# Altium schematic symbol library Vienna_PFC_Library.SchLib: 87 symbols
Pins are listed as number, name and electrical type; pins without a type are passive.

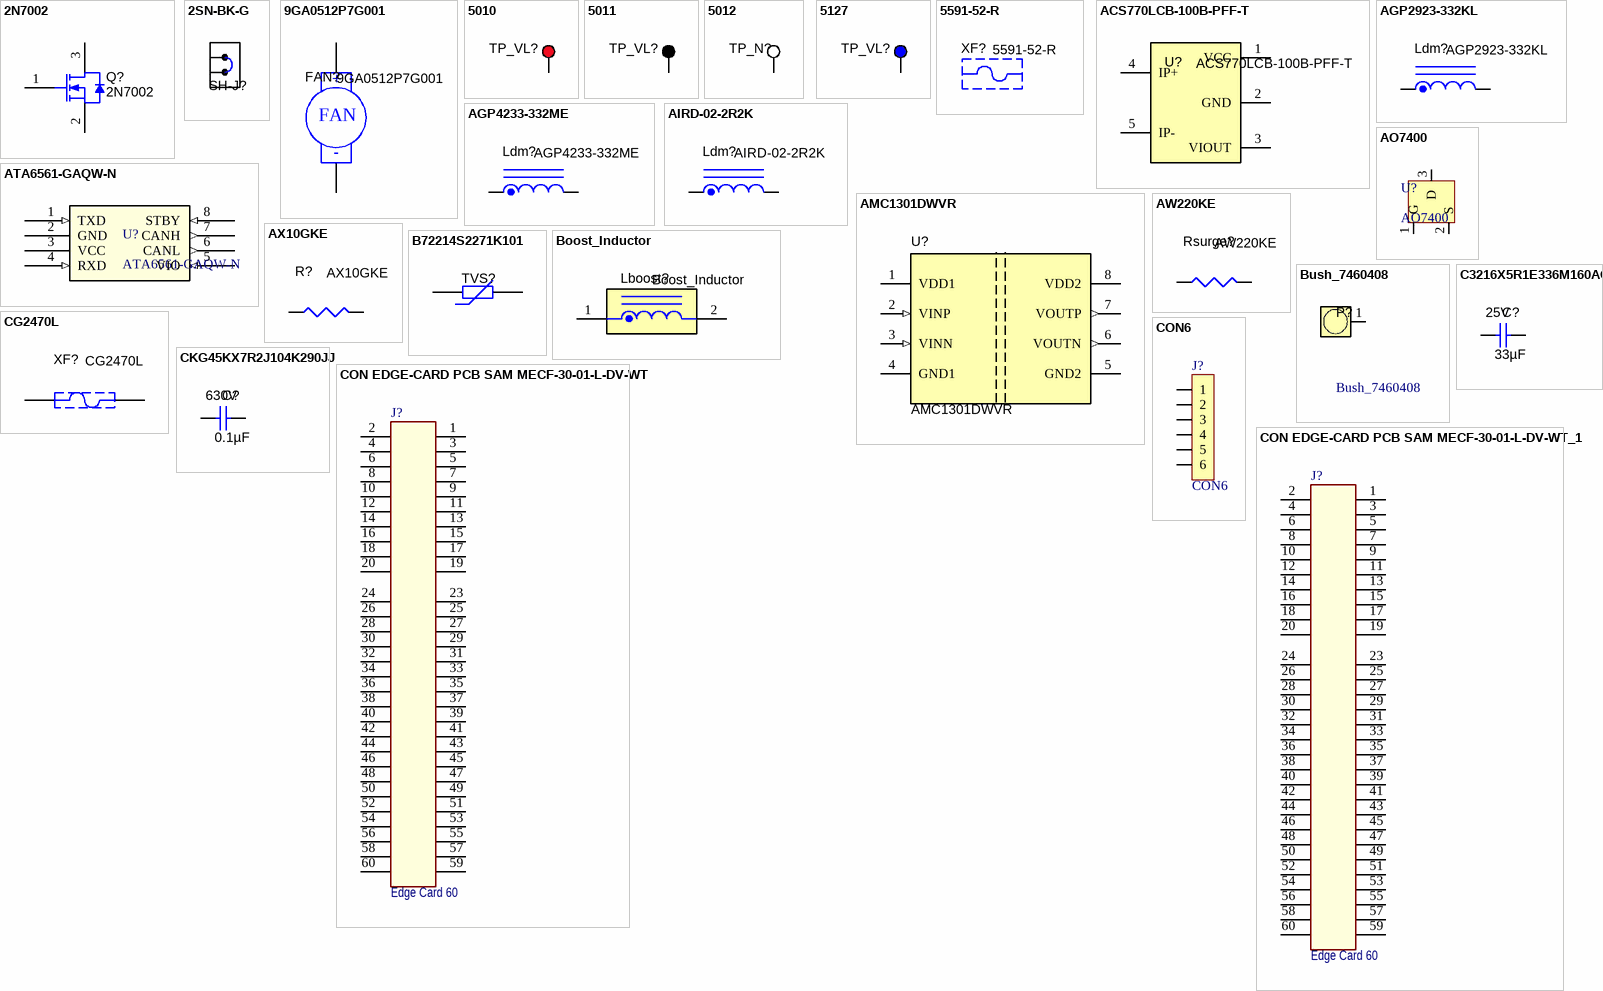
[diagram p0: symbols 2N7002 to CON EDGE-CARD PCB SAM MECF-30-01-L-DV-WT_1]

## 2N7002
designator Q?
MOSFET, N-CH, 60 V, 115 MA, SOT-23; Manufacturer: Fairchild Semiconductor; Alternate Manufacturer: None; U/M: EA; ChType: N; Value: 60V; VdsMax_V: 60; Value1: ? ohm; Value2: ? nC; Vgs_V: 20; IdsMax_A: 115; SizeAreaWB_mm2: 14; SizeArea_mm2: 7.5; SizeX_mm: 2.5; SizeY_mm: 3; SizeZ_mm: 1.1; AEC Category: Q101
footprint SOT-23 (SOT23, 3-Leads, Body 2.9x1.3mm, Pitch 0.95mm, Lead Span 2.5mm, IPC Medium Density)
footprint SOT-23M
footprint SOT-23L
pins: 1 G, 2 S, 3 D

## 2SN-BK-G
designator SH-J?  (value not drawn)
Shunt, 2mm, Gold plated, Black; Manufacturer: Samtec; Value: 1x2; Note: You can "mate" this to a header by matching the designator.  i.e. use SH-J3 for header J3
footprint 2SN-BK-G

## 9GA0512P7G001
designator FAN?
FAN 52X15MM 12VDC TACH,PWM; Manufacturer: Sanyo Denki America Inc.; CompType: DC Fans
pins: 1 +, 2 -

## 5010
designator TP_VL?  (value not drawn)
Test Point, Multipurpose, Red, TH; Manufacturer: Keystone; CompType: Test Point Loop; ContactFinish: Silver
footprint Keystone5010 (Keystone Multipurpose loops)
pins: 1

## 5011
designator TP_VL?  (value not drawn)
Test Point, Multipurpose, Black, TH; Manufacturer: Keystone; CompType: Test Point Loop; ContactFinish: Silver
footprint Keystone5011 (Keystone Multipurpose loops)
pins: 1

## 5012
designator TP_N?  (value not drawn)
Test Point, Multipurpose, White, TH; Manufacturer: Keystone; CompType: Test Point Loop; ContactFinish: Silver
footprint Keystone5012 (Keystone Multipurpose loops)
pins: 1

## 5127
designator TP_VL?  (value not drawn)
Test Point, Multipurpose, Blue, TH; Manufacturer: Keystone; CompType: Test Point Loop; U/M: EA; ContactFinish: Silver
footprint Keystone5127 (Keystone Multipurpose loops)
pins: 1

## 5591-52-R
designator XF?
FUSE CLIP CARTRIDGE CHASSIS MNT, Eaton; CompType: Fuse Holder

## ACS770LCB-100B-PFF-T
designator U?
SENSOR CURRENT HALL 100A AC/DC; Manufacturer: Allegro MicroSystems, LLC; CompType: Current Transducers
footprint ACS770
pins: 1 VCC, 2 GND, 3 VIOUT, 4 IP+, 5 IP-

## AGP2923-332KL
designator Ldm?
FIXED IND 3.3UH 19A 4  TH, Coilcraft; CompType: Fixed Inductors
footprint AGP2923 (Inductor)
pins: 1, 2

## AGP4233-332ME
designator Ldm?
FIXED IND 3.3UH 34A  TH, Coilcraft; CompType: Fixed Inductors
footprint AGP4233-332ME (Inductor)
pins: 1, 2

## AIRD-02-2R2K
designator Ldm?
FIXED IND 2.2UH 11.4A 4 MOHM TH, Abracon LLC; CompType: Fixed Inductors
footprint FuseHolder_65800001009
pins: 1, 2

## AMC1301DWVR
designator U?
Precision +/-250-mV Input, 3-us Delay, Reinforced Isolated Amplifier, DWV0008A (SOIC-8); Manufacturer: Texas Instruments; SymbolCreator: Altium; SizeArea_mm2: 67.275; SizeAreaWB_mm2: 105.975; SizeX_mm: 11.5; SizeY_mm: 5.85; SizeZ_mm: 2.8; CompType: IC; U/M: EA
footprint AMC1301 (SOIC, 8-Leads, Body 5.95x7.6mm (max), Pitch 1.27mm)
pins: 1 VDD1 (power), 2 VINP (in), 3 VINN (in), 4 GND1 (power), 5 GND2 (power), 6 VOUTN (out), 7 VOUTP (out), 8 VDD2 (power)

## AO7400
designator U?
MOSFET N-CH 30V 1.7A SC70-3@785-1084-1-ND
footprint AO7400_SC-70-3L
pins: 1 G, 2 S, 3 D

## ATA6561-GAQW-N
designator U?
CAN Interface IC Industrial Grade CAN TRX with VIO PIN (SO8); Manufacturer: Microchip Technology / Atmel; GENERIC_PART_NUMBER: SN65HVD234; INDUSTRY_STD_PKG_TYPE: SOIC; PIN_COUNT: 8; PACKAGE_DESIGNATOR: D; Vendor: Mouser
footprint SOIC8
pins: 1 TXD (in), 2 GND (power), 3 VCC (power), 4 RXD (in), 5 VIO (in), 6 CANL (out), 7 CANH (out), 8 STBY (in)

## AW220KE
designator Rsurge?
RES 22 OHM 2.5W 10% RADIAL; Manufacturer: Ohmite; CompType: Through Hole Resistors
footprint AW220KE (Capacitor)
pins: 1, 2

## AX10GKE
designator R?
RES 1 OHM 3.5W 10% RADIAL; Manufacturer: Ohmite; CompType: Through Hole Resistors
footprint AX10GKE (Res)
pins: 1, 2

## B72214S2271K101
designator TVS?  (value not drawn)
VARISTOR 430V 6KA DISC 14MM, EPCOS (TDK); CompType: TVS - Varistors, MOVs
footprint B72214S2271K101 (Capacitor)
pins: 1, 2

## Boost_Inductor
designator Lboost?
Boost_Inductor, Handmake
footprint Boost_Inductor
pins: 1, 2

## Bush_7460408
designator P?
TERM PWR ELEMENT M5 12 PIN PCB; Manufacturer: Wurth Electronics Inc.
footprint Bush7460408 (Power Connecter 12pin)
pins: 1 (power) "Voltage input"

## C3216X5R1E336M160AC
designator C?  VDC_V: 25V  ValueDisplayed: 33µF  (hidden comment: C3216X5R1E336M160AC)
CAP, CERM, 33 µF, 25 V, +/- 20%, X5R, 1206; Manufacturer: TDK; Polarized: N; CompType: Capacitor; Value: 33uF; U/M: EA; Tolerance_%: 20; Value1: Unknown; TaMin_C: -55; TaMax_C: 85; Cap_Case: 1206; AEC Category: Q200
signal-integrity model Cap
simulation model Cap
footprint 0805_HV (0805 with 30mil clearance between pads)
pins: 1, 2

## CG2470L
designator XF?
GDT 470V 20KA THROUGH HOLE,  Littelfuse Inc.; CompType: Gas Discharge Tube Arresters (GDT)
footprint CG2470L (Capacitor)
pins: 1, 2

## CKG45KX7R2J104K290JJ
designator C?  VDC_V: 630V  ValueDisplayed: 0.1µF  (hidden comment: CKG45KX7R2J104K290JJ)
CAP, CERM, 0.1 µF, 630V, +/- 10%, X7R, 1206; Value: 33uF; Value1: Unknown; AEC Category: Q200
signal-integrity model Cap
simulation model Cap
footprint 1812 (SMD, 2-Leads, Body 4.8x3.4mm)
pins: 1, 2

## CON6
designator J?
Connector
pins: 1, 2, 3, 4, 5, 6

## CON EDGE-CARD PCB SAM MECF-30-01-L-DV-WT
designator J?  value Edge Card 60  (hidden comment: CON EDGE-CARD PCB SAM MECF-30-01-L-DV-WT)  (no BOM)
MCHP-ID: CON1706; Description_: CON_EDGE-CARD_PCB_SAM_MECF-30-01-L-DV-WT; Dev Tools Status: Design; Owner: Tim Moffat; Populated: YES
footprint CON_EDGE-CARD_PCB_SAM_MECF-30-01-L-DV-WT
footprint CardEdgeConnector60Pin
pins: 1, 2, 3, 4, 5, 6, 7, 8, 9, 10, 11, 12, 13, 14, 15, 16, 17, 18, 19, 20, 23, 24, 25, 26, 27, 28, 29, 30, 31, 32, 33, 34, 35, 36, 37, 38, 39, 40, 41, 42, 43, 44, 45, 46, 47, 48, 49, 50, 51, 52, 53, 54, 55, 56, 57, 58, 59, 60

## CON EDGE-CARD PCB SAM MECF-30-01-L-DV-WT_1
designator J?, comment value Edge Card 60  (hidden comment: CON EDGE-CARD PCB SAM MECF-30-01-L-DV-WT)  (no BOM)
MCHP-ID: CON1706; Description_: CON_EDGE-CARD_PCB_SAM_MECF-30-01-L-DV-WT; Dev Tools Status: Design; Owner: Tim Moffat; Populated: YES
footprint CON_EDGE-CARD_PCB_SAM_MECF-30-01-L-DV-WT
footprint CardEdgeConnector60Pin
pins: 1, 2, 3, 4, 5, 6, 7, 8, 9, 10, 11, 12, 13, 14, 15, 16, 17, 18, 19, 20, 23, 24, 25, 26, 27, 28, 29, 30, 31, 32, 33, 34, 35, 36, 37, 38, 39, 40, 41, 42, 43, 44, 45, 46, 47, 48, 49, 50, 51, 52, 53, 54, 55, 56, 57, 58, 59, 60

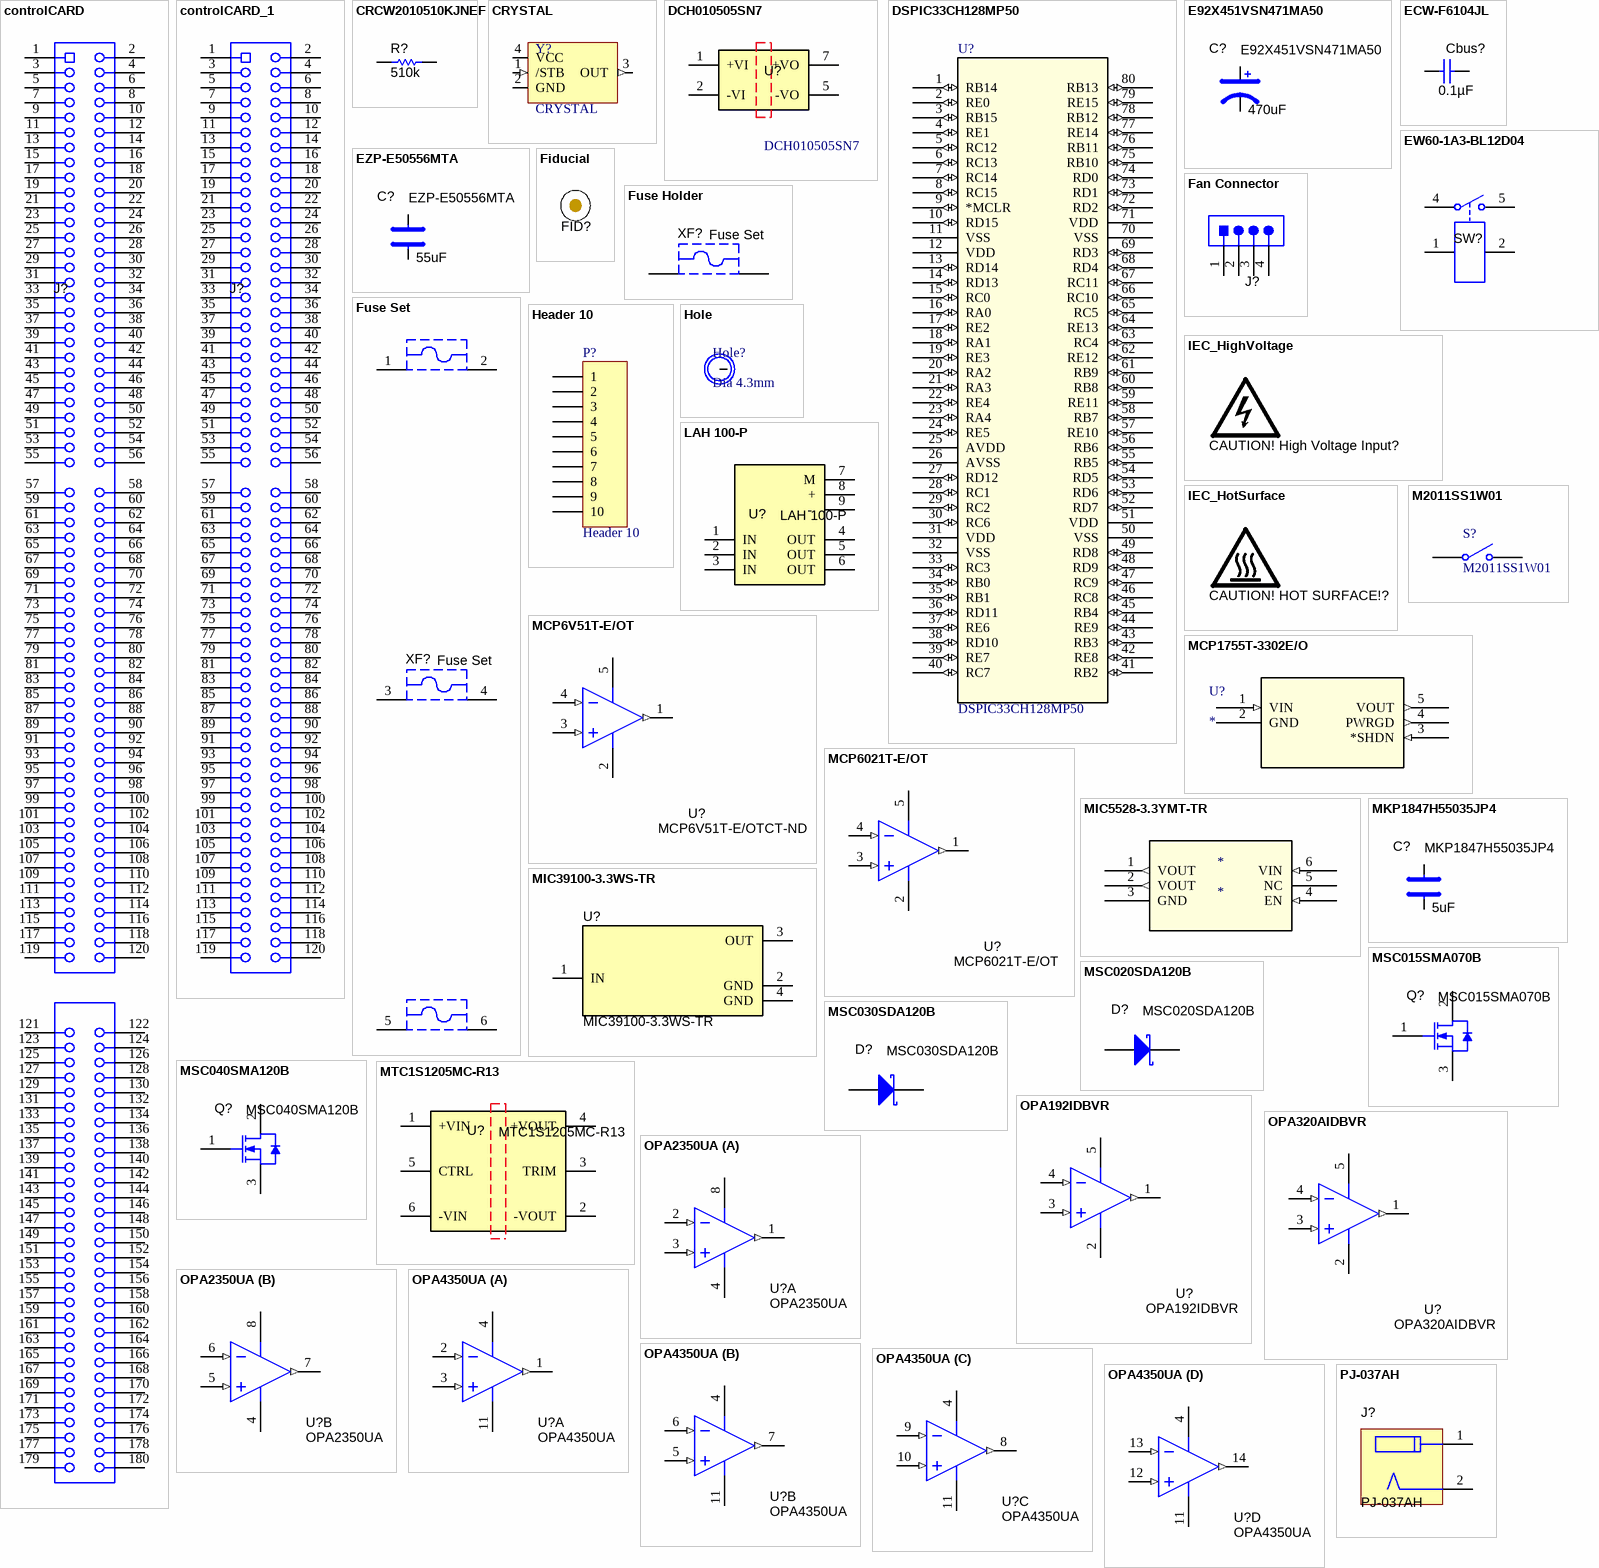
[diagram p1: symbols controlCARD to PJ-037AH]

## controlCARD
designator J?, comment HSEC8-160-01-L-DV-A-BL  (value not drawn)
C2000 controlCARD-180 PIN connector, SMT; Manufacturer: Samtec; SymbolCreator: a0412235; Note: The pin numbering does not match Samtec datasheet
footprint controlCARD-180HSEC (Pads are not numbered according to datasheet.)
pins: 1, 2, 3, 4, 5, 6, 7, 8, 9, 10, 11, 12, 13, 14, 15, 16, 17, 18, 19, 20, 21, 22, 23, 24, 25, 26, 27, 28, 29, 30, 31, 32, 33, 34, 35, 36, 37, 38, 39, 40, 41, 42, 43, 44, 45, 46, 47, 48, 49, 50, 51, 52, 53, 54, 55, 56, 57, 58, 59, 60, 61, 62, 63, 64, 65, 66, 67, 68, 69, 70, 71, 72, 73, 74, 75, 76, 77, 78, 79, 80, 81, 82, 83, 84, 85, 86, 87, 88, 89, 90, 91, 92, 93, 94, 95, 96, 97, 98, 99, 100, 101, 102, 103, 104, 105, 106, 107, 108, 109, 110, 111, 112, 113, 114, 115, 116, 117, 118, 119, 120, 121, 122, 123, 124, 125, 126, 127, 128, 129, 130, 131, 132, 133, 134, 135, 136, 137, 138, 139, 140, 141, 142, 143, 144, 145, 146, 147, 148, 149, 150, 151, 152, 153, 154, 155, 156, 157, 158, 159, 160, 161, 162, 163, 164, 165, 166, 167, 168, 169, 170, 171, 172, 173, 174, 175, 176, 177, 178, 179, 180

## controlCARD_1
designator J?, comment HSEC8-160-01-L-DV-A-BL  (value not drawn)
C2000 controlCARD-160 PIN connector, SMT; Manufacturer: Samtec; SymbolCreator: a0412235; Note: The pin numbering does not match Samtec datasheet
footprint TI_Interface
pins: 1, 2, 3, 4, 5, 6, 7, 8, 9, 10, 11, 12, 13, 14, 15, 16, 17, 18, 19, 20, 21, 22, 23, 24, 25, 26, 27, 28, 29, 30, 31, 32, 33, 34, 35, 36, 37, 38, 39, 40, 41, 42, 43, 44, 45, 46, 47, 48, 49, 50, 51, 52, 53, 54, 55, 56, 57, 58, 59, 60, 61, 62, 63, 64, 65, 66, 67, 68, 69, 70, 71, 72, 73, 74, 75, 76, 77, 78, 79, 80, 81, 82, 83, 84, 85, 86, 87, 88, 89, 90, 91, 92, 93, 94, 95, 96, 97, 98, 99, 100, 101, 102, 103, 104, 105, 106, 107, 108, 109, 110, 111, 112, 113, 114, 115, 116, 117, 118, 119, 120

## CRCW2010510KJNEF
designator R?  ValueDisplayed: 510k  (hidden comment: CRCW2010510KJNEF)
RES, 510 k, 5%, 0.75 W, AEC-Q200 Grade 0, 2010; Manufacturer: Vishay-Dale; CompType: Resistor; Value: 510k; Res_ohm: 510000; Tolerance_%: 5; Power_W: 0.75; Value2: 0.75W; VDC_V: 400; TempCo: 200 ppm/C; SizeArea_mm2: 12.5; SizeY_mm: 2.5; SizeZ_mm: 1.66; EIA_Code: E24; U/M: EA; AEC Category: Q200; AEC Qualified: Y; AEC Grade: 0
signal-integrity model Resistor
simulation model Resistor
footprint 2010
footprint 2010M
footprint 2010L
pins: 1, 2

## CRYSTAL
designator Y?
footprint OSCILLATOR
pins: 1 /STB (in), 2 GND (power), 3 OUT (out), 4 VCC (power)

## DCH010505SN7
designator U?
Miniature, 1 W, 3 kVDC Isolated DC-DC Converter, -40 to 85 degC, 4-pin Module (EDJ4), Pb-Free (RoHS); Manufacturer: Texas Instruments; Alternate PartNumber: Equivalent; Iout(Max)(A): 0.2; Regulated Outputs(#): 1; SubFamily: 1 W & 2 W Miniature; Vin(Max)(V): 5.5; Vin(Min)(V): 4.5
footprint DCH010505SN7 (Module, 4-Leads, Body 19.56x7.62mm)
pins: 1 +VI (power) "Voltage input", 2 -VI (power) "Input side common", 5 -VO (power) "-Voltage out", 7 +VO (power) "+Voltage out"

## DSPIC33CH128MP50
designator U?
Imported; Manufacturer_Part_Number: DSPIC33CH128MP508; Vendor: Microchip; Built_By: EMA_Jessica; C: Copyright (C) 2016 Accelerated Designs. All rights reserved
footprint TQFP80_12x12MC
pins: 1 RB14 (io), 2 RE0 (io), 3 RB15 (io), 4 RE1 (io), 5 RC12 (io), 6 RC13 (io), 7 RC14 (io), 8 RC15 (io), 9 *MCLR (io), 10 RD15 (io), 11 VSS (power), 12 VDD (power), 13 RD14 (io), 14 RD13 (io), 15 RC0 (io), 16 RA0 (io), 17 RE2 (io), 18 RA1 (io), 19 RE3 (io), 20 RA2 (io), 21 RA3 (io), 22 RE4 (io), 23 RA4 (io), 24 RE5 (io), 25 AVDD (power), 26 AVSS (power), 27 RD12 (io), 28 RC1 (io), 29 RC2 (io), 30 RC6 (io), 31 VDD (power), 32 VSS (power), 33 RC3 (io), 34 RB0 (io), 35 RB1 (io), 36 RD11 (io), 37 RE6 (io), 38 RD10 (io), 39 RE7 (io), 40 RC7 (io), 41 RB2 (io), 42 RE8 (io), 43 RB3 (io), 44 RE9 (io), 45 RB4 (io), 46 RC8 (io), 47 RC9 (io), 48 RD9 (io), 49 RD8 (io), 50 VSS (power), 51 VDD (power), 52 RD7 (io), 53 RD6 (io), 54 RD5 (io), 55 RB5 (io), 56 RB6 (io), 57 RE10 (io), 58 RB7 (io), 59 RE11 (io), 60 RB8 (io), 61 RB9 (io), 62 RE12 (io), 63 RC4 (io), 64 RE13 (io), 65 RC5 (io), 66 RC10 (io), 67 RC11 (io), 68 RD4 (io), 69 RD3 (io), 70 VSS (power), 71 VDD (power), 72 RD2 (io), 73 RD1 (io), 74 RD0 (io), 75 RB10 (io), 76 RB11 (io), 77 RE14 (io), 78 RB12 (io), 79 RE15 (io), 80 RB13 (io)

## E92X451VSN471MA50
designator C?  value 470uF
Aluminum Electrolytic Capacitors - Snap In 450V 470uF 20% Long Life; Manufacturer: United Chemi-Con (UCC)
footprint E92X451VSN471MA50 (Capacitor)
pins: 1, 2

## ECW-F6104JL
designator Cbus?  ValueDisplayed: 0.1µF  (hidden comment: ECW-F6104JL)
CAP, Film, 0.1 µF, 630 V, +/- 5%, TH; Manufacturer: Panasonic; Polarized: N; CompType: Capacitor; Value: 0.1uF; U/M: EA; Cap_F: 0.0000001; Tolerance_%: 5; Value1: Unknown; VDC_V: 630; Value2: 630V; TaMin_C: -40; TaMax_C: 105; Cap_Case: Radial 18x7.7x13.6; AEC Category: Q200
signal-integrity model Cap
simulation model Cap
footprint ECW-F6104JL (PANASONIC)
pins: 1, 2

## EW60-1A3-BL12D04
designator SW?, comment EW60-1A3-BL12D04,00000
RELAY GEN PURPOSE SPST 60A 12V; Manufacturer: TE Connectivity Potter & Brumfield Relays; CompType: Power Relays
footprint EW60-1A3-BL12D04,00000 (Capacitor)
pins: 1, 2, 4, 5

## EZP-E50556MTA
designator C?  value 55uF
CAP FILM 55UF 10% 500VDC RAD 4LD; Manufacturer: Panasonic Electronic Components; CompType: Film Capacitors
footprint EZP-E50556MTA (Capacitor)
pins: 1, 2

## Fan Connector
designator J?  (value not drawn)
4 Positions Header Connector 0.100" (2.54mm) Through Hole Tin; Manufacturer: TE Connectivity AMP Connectors
footprint Fan Connector
pins: 1 GND_BLACK, 2 +VCC_RED, 3 SENSE_YELLOW, 4 CONTROL_BLUE
1 alternate drawing of the same symbol

## Fiducial
designator FID?  (value not drawn)
Fiducial mark.  There is nothing to buy or mount.; SymbolCreator: codlsc
footprint Fiducial10-30
footprint Fiducial10-20
footprint Fiducial15-30
footprint Fiducial20-40
footprint Fiducial6.4-20

## Fuse Holder
designator XF?, comment Fuse Set
2*5591-52-R, 1*50C14X51AM
footprint FuseHolde_5591-52-R (SMD, 2-Leads, Body 22.7x10.8mm, Pitch 17mm)
pins: 1, 2

## Fuse Set
designator XF?
6*5591-52-R, 3*50C14X51AM
footprint FuseHolde_Set
pins: 1, 2, 3, 4, 5, 6

## Header 10
designator P?
Header, 10-Pin
footprint HDR1X10 (Connector; Header; 10 Position)
signal-integrity model Connector
pins: 1, 2, 3, 4, 5, 6, 7, 8, 9, 10

## Hole
designator Hole?, comment Dia 4.3mm
Hole  Dia 4.3mm
footprint Hole-Dia 4.3mm
pins: 0

## IEC_HighVoltage
designator CAUTION! High Voltage Input?, comment DANGER HIGH VOLTAGE  (value not drawn)  (no BOM)
IEC 61010-1 High Voltage Warning; SymbolCreator: a0412235
footprint IEC_HighVoltage_Large
footprint IEC_HighVoltage_Medium
footprint IEC_HighVoltage_Small

## IEC_HotSurface
designator CAUTION! HOT SURFACE!?, comment CAUTION HOT SURFACE  (value not drawn)  (no BOM)
IEC 61010-1 Hot Surface Warning; SymbolCreator: a0412235
footprint IEC_HotSurface_Large
footprint IEC_HotSurface_Medium
footprint IEC_HotSurface_Small

## LAH 100-P
designator U?
SENSOR CURRENT HALL 100A AC/DC; Manufacturer: LEM USA Inc.; CompType: Current Transducers
footprint LAH 100-P (Inductor)
pins: 1 IN, 2 IN, 3 IN, 4 OUT, 5 OUT, 6 OUT, 7 M (power), 8 + (power), 9 - 

## M2011SS1W01
designator S?
footprint M2011SS1W01 (Capacitor)
pins: 2 COMMON, 3 NO

## MCP6V51T-E/OT
designator U?, comment MCP6V51T-E/OTCT-ND
SINGLE, 45V ZERO-DRIFT OP AMP, E; Alternate Manufacturer: Microchip Technology
footprint OPA192 (SOT23, 5-Leads, Body 2.9x1.6mm, Pitch 0.95mm, Lead Span 2.8mm, IPC Medium Density)
footprint DBV0005A_L (SOT23, 5-Leads, Body 2.9x1.6mm, Pitch 0.95mm, IPC Low Density)
footprint DBV0005A_M (SOT23, 5-Leads, Body 2.9x1.6mm, Pitch 0.95mm, IPC Low Density)
pins: 1 OUT (out), 2 V- (power), 3 IN+ (in), 4 IN- (in), 5 V+ (power)

## MCP1755T-3302E/O
designator U?
Imported; Manufacturer_Part_Number: MCP1755T-3302E/OT; Vendor: Microchip; Built_By: EMA_UL_Team; C: Copyright (C) 2015 Accelerated Designs. All rights reserved
footprint SOT-23-5_MC
pins: 1 VIN (in), 2 GND (power), 3 *SHDN (in), 4 PWRGD (out), 5 VOUT (out)

## MCP6021T-E/OT
designator U?
General Purpose Amplifier 1 Circuit Rail-to-Rail SOT-23-5; Manufacturer: Microchip Technology; Number of Channels: 2; Offset Drift(Typ)(uV/C): 1.5; Total Supply Voltage(Max)(+5V is 5, +/-5V is 10): 5.5; Total Supply Voltage(Min)(+5V is 5, +/-5V is 10): 2.5
footprint OPA320 (SOT23, 5-Leads, Body 2.9x1.6mm, Pitch 0.95mm, Lead Span 2.8mm, IPC Medium Density)
footprint DBV0005A_L (SOT23, 5-Leads, Body 2.9x1.6mm, Pitch 0.95mm, IPC Low Density)
footprint DBV0005A_M (SOT23, 5-Leads, Body 2.9x1.6mm, Pitch 0.95mm, IPC Low Density)
pins: 1 OUT (out), 2 V- (power), 3 IN+ (in), 4 IN- (in), 5 V+ (power)

## MIC5528-3.3YMT-TR
designator *
footprint 6-Lead Thin DFN
pins: 1 VOUT (out), 2 VOUT (out), 3 GND (power), 4 EN (in), 5 NC, 6 VIN (in)

## MIC39100-3.3WS-TR
designator U?
Linear Voltage Regulator IC  1 Output  1A SOT-223; Manufacturer: Microchip Technology
footprint TLV1117 (SOT223/SC73, 4-Leads, Body 6.5x3.5mm, Pitch 2.3mm, Lead Span 7mm, IPC Medium Density)
footprint DCY0004A_M
footprint DCY0004A_L
pins: 1 IN (power), 2 GND (power), 3 OUT (power), 4 GND (power)

## MKP1847H55035JP4
designator C?  value 5uF
CAP FILM 5UF 5% 700VDC RAD 4LDS; Manufacturer: Vishay BC Components; CompType: Film Capacitors
footprint MKP1847H55035JP4 (Capacitor)
pins: 1, 2

## MSC015SMA070B
designator Q?
GEN2 SIC MOSFET 700V 15MOHM TO-247-3; Manufacturer: Microsemi Corporation; CompType: Transistors - FETs, MOSFETs - Single
footprint TO-247
pins: 1 G, 2 D, 3 S

## MSC020SDA120B
designator D?
DIODE SCHOTTKY 1.2KV 43A TO247; Manufacturer: Microsemi Corporation; CompType: Diodes - Rectifiers - Single
footprint FuseHolder_65800001009
pins: 1 K, 2 A

## MSC030SDA120B
designator D?
DIODE SCHOTTKY 1.2KV 30A TO247; Manufacturer: Microsemi Corporation; CompType: Diodes - Rectifiers - Single
footprint TO-247-ress
pins: 1 K, 2 A

## MSC040SMA120B
designator Q?
MOSFET N-CH 1200V TO247; Manufacturer: Microsemi Corporation; CompType: Transistors - FETs, MOSFETs - Single
footprint TO-247
pins: 1 G, 2 D, 3 S

## MTC1S1205MC-R13
designator U?
CONV DC/DC 5V 1W; Manufacturer: Murata Power Solutions Inc.; CompType: DC DC Converters
footprint FuseHolder_65800001009
pins: 1 +VIN, 2 -VOUT, 3 TRIM, 4 +VOUT, 5 CTRL, 6 -VIN

## OPA192IDBVR
designator U?
IC OP AMP RRIO E-TRIM SOT23-5; Alternate Manufacturer: Texas Instruments
footprint OPA192 (SOT23, 5-Leads, Body 2.9x1.6mm, Pitch 0.95mm, Lead Span 2.8mm, IPC Medium Density)
footprint DBV0005A_L (SOT23, 5-Leads, Body 2.9x1.6mm, Pitch 0.95mm, IPC Low Density)
footprint DBV0005A_M (SOT23, 5-Leads, Body 2.9x1.6mm, Pitch 0.95mm, IPC Low Density)
pins: 1 OUT (out), 2 V- (power), 3 IN+ (in), 4 IN- (in), 5 V+ (power)

## OPA320AIDBVR
designator U?
Precision, 20 MHz, 0.9 pA Ib, RRIO, CMOS Operational Amplifier, 1.8 to 5.5 V, -40 to 125 degC, 5-pin SOT23 (DBV0005A), Green (RoHS & no Sb/Br); Manufacturer: Texas Instruments; Alternate PartNumber: Equivalent; CMRR(Min)(dB): 100; IIB(Max)(pA): 0.9; Iq per channel(Max)(mA): 1.75; Number of Channels: 2; Offset Drift(Typ)(uV/C): 1.5; Slew Rate(Typ)(V/us): 10; Sub Family: High Output Current Amplifier (>=50mA), Low Input Bias Current Amp (<=10pA), Low Noise Amp (<=10nV/rtHz), Low Offset Voltage Amplifier (<=500uV), Low Supply Voltage Amplifier (<=2.7V), Precision Amplifier; Total Supply Voltage(Max)(+5V is 5, +/-5V is 10): 5.5; Total Supply Voltage(Min)(+5V is 5, +/-5V is 10): 1.8; Vio (25C)(Max)(mV): 0.15; Vn at 1kHz(Typ)(nV/rtHz): 8.5
footprint OPA320 (SOT23, 5-Leads, Body 2.9x1.6mm, Pitch 0.95mm, Lead Span 2.8mm, IPC Medium Density)
footprint DBV0005A_L (SOT23, 5-Leads, Body 2.9x1.6mm, Pitch 0.95mm, IPC Low Density)
footprint DBV0005A_M (SOT23, 5-Leads, Body 2.9x1.6mm, Pitch 0.95mm, IPC Low Density)
pins: 1 OUT (out), 2 V- (power), 3 IN+ (in), 4 IN- (in), 5 V+ (power)

## OPA2350UA
designator U?
IC OPAMP GP 38MHZ RRO 8SOIC; Manufacturer: Texas Instruments; Alternate PartNumber: Equivalent; CMRR(Min)(dB): 66; IIB(Max)(pA): 10; Iq per channel(Max)(mA): 7.5; Slew Rate(Typ)(V/us): 22; Sub Family: Low Input Bias Current Amp (<=10pA), Low Offset Voltage Amplifier (<=500uV), Low Supply Voltage Amplifier (<=2.7V), Precision Amplifier; Total Supply Voltage(Max)(+5V is 5, +/-5V is 10): 5.5; Total Supply Voltage(Min)(+5V is 5, +/-5V is 10): 2.7; Vio (25C)(Max)(mV): 0.5; Vn at 1kHz(Typ)(nV/rtHz): 18
footprint SOIC8
footprint D0014A_L (SOIC, 14-Leads, Body 8.65x3.9mm, Pitch 1.27mm, IPC High Density)
footprint D0014A_M (SOIC, 14-Leads, Body 8.65x3.9mm, Pitch 1.27mm, IPC Low Density)
pins on every part: 4 V- (power), 8 V+ (power)
part A pins: 1 OUT A (out), 2 IN A- (in), 3 IN A+ (in)
part B pins: 5 IN B+ (in), 6 IN B- (in), 7 OUT B (out)

## OPA4350UA
designator U?
High-Speed, Single-Supply, Rail-to-Rail Operational Amplifier MicroAmplifier(TM) Series, 2.7 to 5.5 V, -55 to 150 degC, 14-pin SOIC (D0014A), Green (RoHS & no Sb/Br); Manufacturer: Texas Instruments; Alternate PartNumber: Equivalent; CMRR(Min)(dB): 66; IIB(Max)(pA): 10; Iq per channel(Max)(mA): 7.5; Number of Channels: 4; Slew Rate(Typ)(V/us): 22; Sub Family: Low Input Bias Current Amp (<=10pA), Low Offset Voltage Amplifier (<=500uV), Low Supply Voltage Amplifier (<=2.7V), Precision Amplifier; Total Supply Voltage(Max)(+5V is 5, +/-5V is 10): 5.5; Total Supply Voltage(Min)(+5V is 5, +/-5V is 10): 2.7; Vio (25C)(Max)(mV): 0.5; Vn at 1kHz(Typ)(nV/rtHz): 18
footprint OPA4350 (SOIC, 14-Leads, Body 8.7x3.9mm, Pitch 1.27mm, IPC Medium Density)
footprint D0014A_L (SOIC, 14-Leads, Body 8.65x3.9mm, Pitch 1.27mm, IPC High Density)
footprint D0014A_M (SOIC, 14-Leads, Body 8.65x3.9mm, Pitch 1.27mm, IPC Low Density)
pins on every part: 4 V+ (power), 11 V- (power)
part A pins: 1 OUT A (out), 2 IN A- (in), 3 IN A+ (in)
part B pins: 5 IN B+ (in), 6 IN B- (in), 7 OUT B (out)
part C pins: 8 OUT C (out), 9 IN C- (in), 10 IN C+ (in)
part D pins: 12 IN D+ (in), 13 IN D- (in), 14 OUT D (out)

## PJ-037AH
designator J?
Power Jack, 2mm, R/A, TH; Manufacturer: CUI Inc.; SymbolCreator: Altium; Pitch_mm: 6; Gender: Male; Shrouded: N; Row_Count: 1
footprint PJ-037AH (Power Jack, 2mm, R/A, TH)
pins: 1, 2

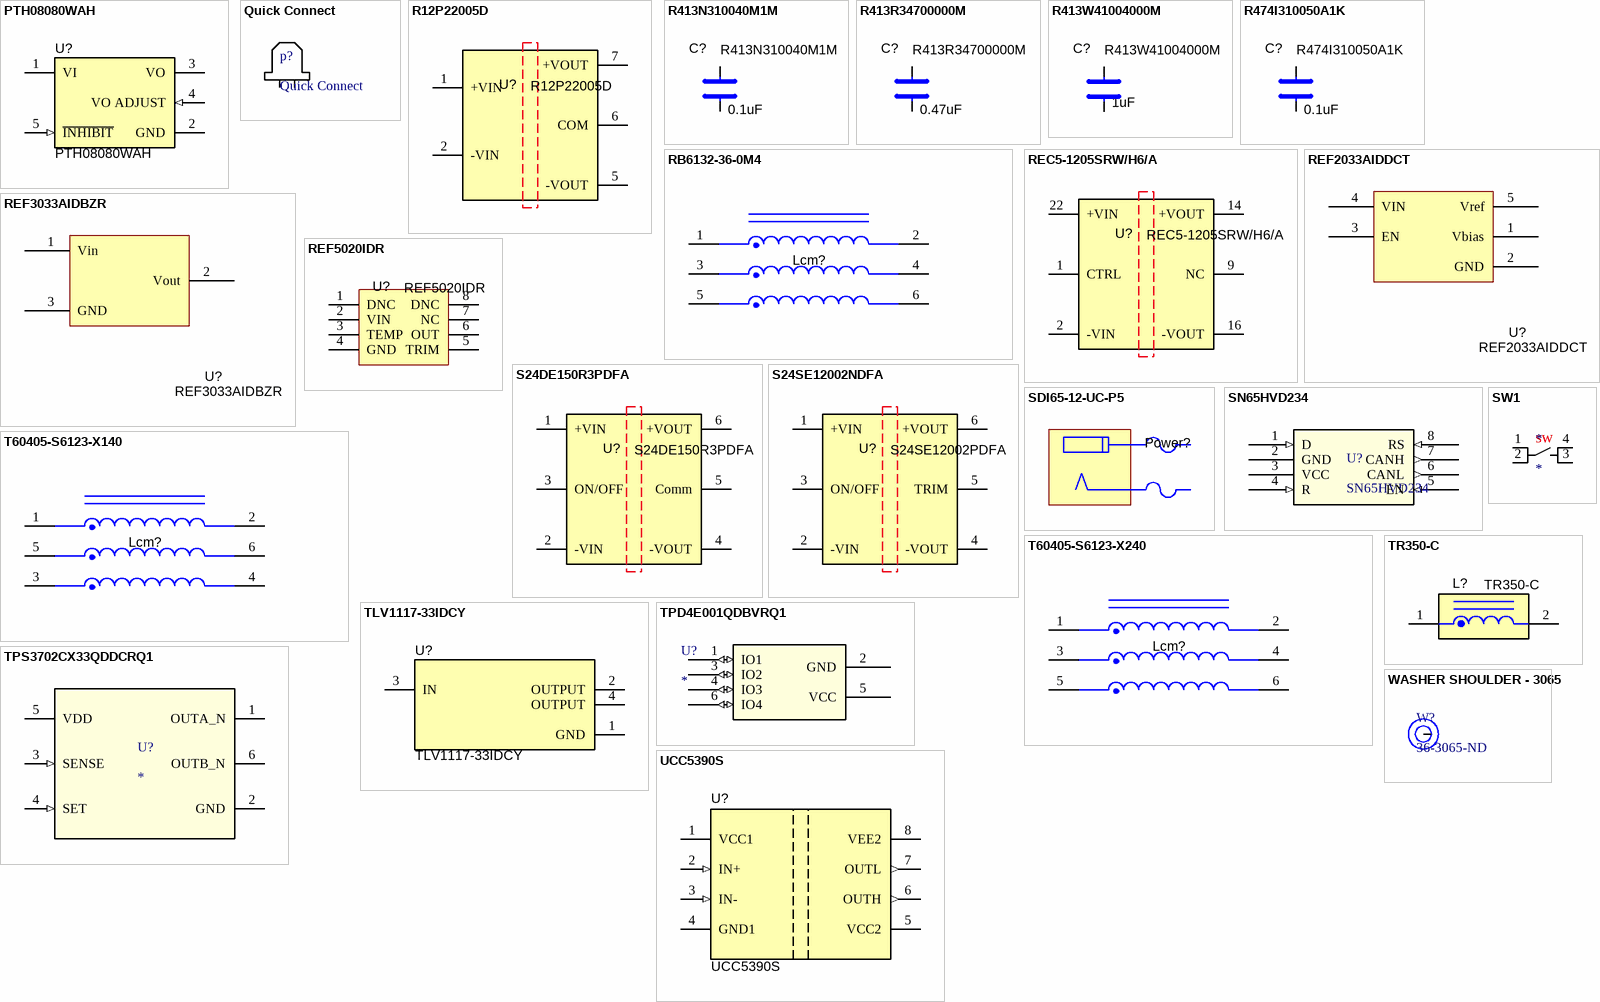
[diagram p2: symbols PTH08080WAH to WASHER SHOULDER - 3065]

## PTH08080WAH
designator U?
2.25 A, 4.5 to 18 V Input Wide Adjust Miniature Power Module, -40 to 85 degC, 5-pin Module (EUF5), Pb-Free (RoHS); Manufacturer: Texas Instruments; Alternate PartNumber: Equivalent; Iout(Max)(A): 2.25; Regulated Outputs(#): 1; SubFamily: Non-Isolated POL; Vin(Max)(V): 18; Vin(Min)(V): 4.5; VO Adjustable: TRUE; Vout(Max)(V): 5.5; Vout(Min)(V): 0.9
footprint PTH08080WAH
pins: 1 VI (power) "The positive input voltage power node to the module, which is referenced to common GND.", 2 GND (power) "This is the common ground connection for the VI and VO power connections. It is also the 0-Vdc reference for the Inhibit and VO Adjust control inputs.", 3 VO (power) "The regulated positive power output with respect to the GND node.", 4 VO ADJUST (in) "A 1% resistor must be connected between this pin and GND (pin 1) to set the output voltage of the module higher than 0.9 V. If left open-circuit, the output voltage defaults to this value. The temperature stability of the (See Datasheet)", 5 ~{INHIBIT} (in) "The Inhibit pin is an open-collector/drain-negative logic input that is referenced to GND. Applying a low-level ground signal to this input disables the module's output. When the Inhibit control is active, the input current (See Datasheet)"

## Quick Connect
designator p?
0.187" (4.75mm) Quick Connect Male Solder
footprint Quick Connect-4.75mm
pins: 1, 1

## R12P22005D
designator U?
CONV DC/DC 2W 12VIN +20/-5VOUT T; Manufacturer: Recom Power; CompType: DC DC Converters
footprint R12P22005D
pins: 1 +VIN, 2 -VIN, 5 -VOUT, 6 COM, 7 +VOUT

## R413N310040M1M
designator C?  value 0.1uF
CAP FILM 0.1UF 20% 1KVDC RADIAL; Manufacturer: KEMET; CompType: Film Capacitors
footprint R413N310040M1M (Capacitor)
pins: 1, 2

## R413R34700000M
designator C?  value 0.47uF
CAP FILM 0.47UF 20% 1KVDC RADIAL; Manufacturer: KEMET; CompType: Film Capacitors
footprint R413R34700000M (Capacitor)
pins: 1, 2

## R413W41004000M
designator C?  value 1uF
CAP FILM 1UF 20% 1KVDC RADIAL; Manufacturer: KEMET; CompType: Film Capacitors
footprint R413W41004000M (Capacitor)
pins: 1, 2

## R474I310050A1K
designator C?  value 0.1uF
CAP FILM 0.1UF 10% 1KVDC RADIAL; Manufacturer: KEMET; CompType: Film Capacitors
footprint FuseHolder_65800001009
pins: 1, 2

## RB6132-36-0M4
designator Lcm?
CMC 420UH 36A 3LN TH; Manufacturer: Schaffner EMC Inc.; CompType: Common Mode Chokes
footprint RB6132-36-0M4 (Common mode choke)
pins: 1, 2, 3, 4, 5, 6

## REC5-1205SRW/H6/A
designator U?
CONV DC/DC 5W 9-18VIN 05VOUT; Manufacturer: Recom Power; CompType: DC DC Converters
footprint FuseHolder_65800001009
pins: 1 CTRL, 2 -VIN, 9 NC, 14 +VOUT, 16 -VOUT, 22 +VIN

## REF2033AIDDCT
designator U?
IC VREF SERIES 1.65V/3.3V 5SOT; Manufacturer: Texas Instruments; Number of Channels: 2
footprint OPA320 (SOT23, 5-Leads, Body 2.9x1.6mm, Pitch 0.95mm, Lead Span 2.8mm, IPC Medium Density)
footprint DBV0005A_L (SOT23, 5-Leads, Body 2.9x1.6mm, Pitch 0.95mm, IPC Low Density)
footprint DBV0005A_M (SOT23, 5-Leads, Body 2.9x1.6mm, Pitch 0.95mm, IPC Low Density)
pins: 1 Vbias, 2 GND, 3 EN, 4 VIN, 5 Vref

## REF3033AIDBZR
designator U?
IC VREF SERIES 3.3V SOT23-3; Manufacturer: Texas Instruments; Number of Channels: 2
footprint SOT-23 (SOT23, 3-Leads, Body 2.9x1.3mm, Pitch 0.95mm, Lead Span 2.5mm, IPC Medium Density)
footprint DBV0005A_L (SOT23, 5-Leads, Body 2.9x1.6mm, Pitch 0.95mm, IPC Low Density)
footprint DBV0005A_M (SOT23, 5-Leads, Body 2.9x1.6mm, Pitch 0.95mm, IPC Low Density)
pins: 1 Vin, 2 Vout, 3 GND

## REF5020IDR
designator U?
IC VREF SERIES 2.048V 8SOIC; Manufacturer: Texas Instruments; CompType: PMIC
footprint SOIC8
pins: 1 DNC, 2 VIN, 3 TEMP, 4 GND, 5 TRIM, 6 OUT, 7 NC, 8 DNC

## S24DE150R3PDFA
designator U?
DC/DC CONVERT +/-15V 330MA 6DIP; Manufacturer: Delta Electronics; CompType: DC DC Converters
footprint S24SE12002NDFA
pins: 1 +VIN, 2 -VIN, 3 ON/OFF, 4 -VOUT, 5 Comm, 6 +VOUT

## S24SE12002NDFA
designator U?, comment S24SE12002PDFA
DC/DC CONVERTER 12V 1.67A 6DIP; Manufacturer: Delta Electronics; CompType: DC DC Converters
footprint S24SE12002NDFA
pins: 1 +VIN, 2 -VIN, 3 ON/OFF, 4 -VOUT, 5 TRIM, 6 +VOUT

## SDI65-12-UC-P5
designator Power?  (mechanical)
AC/DC DESKTOP ADAPTER 12V 60W; Manufacturer: CUI Inc.

## SN65HVD234
designator U?
IC CAN TRANSCEIVER 3.3V 8-SOIC; Manufacturer: Texas Instruments; Manufacturer_Part_Number: sn65hvd235_d_8; INDUSTRY_STD_PKG_TYPE: SOIC; PIN_COUNT: 8; PACKAGE_DESIGNATOR: D
footprint SOIC8
pins: 1 D (in), 2 GND (power), 3 VCC (power), 4 R (in), 5 EN (in), 6 CANL (out), 7 CANH (out), 8 RS (in)

## SW1
designator *
pins: 1, 2, 3, 4

## T60405-S6123-X140
designator Lcm?
Common Mode Chokes / Filters 580 uH 40A horiz. 2.5mH; Manufacturer: Vacuumschmelze
footprint T60405-S6123-X140 (Common mode choke)
pins: 1, 2, 3, 4, 5, 6

## T60405-S6123-X240
designator Lcm?
Common Mode Chokes / Filters CM Choke 3 phase 40A horiz. 1.5mH; Manufacturer: Vacuumschmelze
footprint T60405-S6123-X240 (Common mode choke)
pins: 1, 2, 3, 4, 5, 6

## TLV1117-33IDCY
designator U?
FIXED LOW-DROPOUT VOLTAGE REGULATOR, DCY0004A; Manufacturer: Texas Instruments; SymbolCreator: a0411947; SizeArea_mm2: 45.5; SizeAreaWB_mm2: 76.5; SizeX_mm: 7; SizeY_mm: 6.5; SizeZ_mm: 1.8; CompType: IC; U/M: EA
footprint TLV1117 (SOT223/SC73, 4-Leads, Body 6.5x3.5mm, Pitch 2.3mm, Lead Span 7mm, IPC Medium Density)
footprint DCY0004A_M
footprint DCY0004A_L
pins: 1 GND (power), 2 OUTPUT (power), 3 IN (power), 4 OUTPUT (power)

## TPD4E001QDBVRQ1
designator U?
Imported; Manufacturer_Part_Number: TPD4E001QDBVRQ1; Vendor: Texas Instruments; Built_By: EMA_UL_Team; C: Copyright (C) 2015 Accelerated Designs. All rights reserved
footprint DBV6
footprint DBV6
pins: 1 IO1 (io), 2 GND (power), 3 IO2 (io), 4 IO3 (io), 5 VCC (power), 6 IO4 (io)

## TPS3702CX33QDDCRQ1
designator U?
Imported; PartNumber: TPS3702CX33QDDCRQ1; Manufacturer: Texas Instruments; CompType: IC; PIN_COUNT: 6
footprint DDC0006A_N
pins: 1 OUTA_N (oc), 2 GND (power), 3 SENSE (in), 4 SET (in), 5 VDD (power), 6 OUTB_N (oc)

## TR350-C
designator L?
Manufacturer: Lodestone Pacific; CompType: Torroid Retainer
footprint FuseHolder_65800001009
pins: 1, 2

## UCC5390S
designator U?
Isolated Gate Drivers with High CMTI and Scalable Drive Strength, D0008B (SOIC-8); Manufacturer: Texas Instruments; SymbolCreator: a0411947; SizeArea_mm2: 29.4; SizeAreaWB_mm2: 55.2; SizeX_mm: 6; SizeY_mm: 4.9; SizeZ_mm: 1.75; CompType: IC; U/M: EA
footprint UCC5390S (SOIC, 8-Leads, Body 5.95x7.6mm (max), Pitch 1.27mm)
footprint D0008B_N
footprint D0008B_M
footprint D0008B_L
pins: 1 VCC1 (power), 2 IN+ (in), 3 IN- (in), 4 GND1 (power), 5 VCC2 (power), 6 OUTH (out), 7 OUTL (out), 8 VEE2 (power)

## WASHER SHOULDER - 3065
designator W?, comment 36-3065-ND
WASHER SHOULDER #8 FIBRE
footprint WASHER SHOULDER
pins: 0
